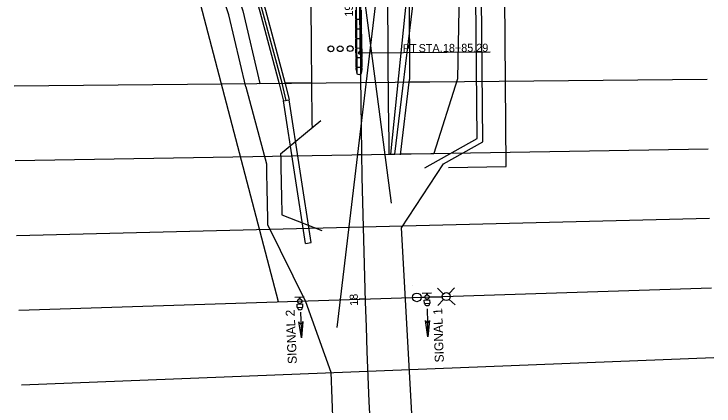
# Model space of a CAD drawing. Extents: x 2283072 to 2287933, y 586198 to 587702.
# Drawn here: x 2284314.5 to 2284556.9, y 586950.6 to 587086.3 of the extents above; entities that cross this region are included whole.
import ezdxf

# ---------------------------------------------------------------- set-up
doc = ezdxf.new("R2010")
doc.units = 0
for name, color, linetype in [('_CIVIL_CONSTRUCTION', 7, 'Continuous'), ('DR_X_Ditch', 7, 'Continuous'), ('DR_X_Headwall', 7, 'Continuous'), ('DT_X_Contour_Major', 7, 'Continuous'), ('DT_X_Terrain_Boundary', 7, 'Continuous'), ('DT_X_Void', 7, 'Continuous'), ('PF_X_Ground_Line', 7, 'Continuous'), ('PV_X_EOP', 7, 'Continuous'), ('RD_P_Fence', 7, 'Continuous'), ('RD_X_Gate', 7, 'Continuous'), ('RS_Raster1', 7, 'Continuous'), ('RW_P_Esmt_SH', 7, 'Continuous'), ('RW_P_Esmt_TMP', 7, 'Continuous'), ('SV_X_Break_Lines', 7, 'Continuous'), ('SV_X_Random_Point', 7, 'Continuous'), ('SV_X_Toe_of_Slope', 7, 'Continuous'), ('UT_X_Overhead_Telecom', 7, 'Continuous')]:
    doc.layers.add(name, color=color, linetype=linetype)

msp = doc.modelspace()

# ---------------------------------------------------------------- linework, layer by layer
at = {"layer": '_CIVIL_CONSTRUCTION'}
for p, q in [((2284442.67, 587114.69), (2284426.32, 586977.76)), ((2284452.67, 587114.75), (2284444.91, 587037.77)), ((2284433.32, 587065.57), (2284433.15, 587091.06)), ((2284434.49, 587091.07), (2284434.65, 587065.58)), ((2284432.86, 587084.56), (2284432.84, 587087.56)), ((2284434.86, 587084.57), (2284434.84, 587087.57)), ((2284432.86, 587084.56), (2284433.03, 587084.39)), ((2284433.03, 587084.39), (2284432.87, 587084.23)), ((2284432.89, 587081.23), (2284432.87, 587084.23)), ((2284434.7, 587084.41), (2284433.03, 587084.39)), ((2284434.86, 587084.57), (2284434.7, 587084.41)), ((2284434.7, 587084.41), (2284434.87, 587084.24)), ((2284434.89, 587081.24), (2284434.87, 587084.24)), ((2284432.89, 587081.23), (2284433.05, 587081.06)), ((2284433.05, 587081.06), (2284432.89, 587080.89)), ((2284432.91, 587077.89), (2284432.89, 587080.89)), ((2284434.72, 587081.07), (2284433.05, 587081.06)), ((2284434.89, 587081.24), (2284434.72, 587081.07)), ((2284434.72, 587081.07), (2284434.89, 587080.91)), ((2284434.91, 587077.91), (2284434.89, 587080.91)), ((2284432.91, 587077.89), (2284433.08, 587077.73)), ((2284433.08, 587077.73), (2284432.91, 587077.56)), ((2284434.74, 587077.74), (2284433.08, 587077.73)), ((2284434.91, 587077.91), (2284434.74, 587077.74)), ((2284434.74, 587077.74), (2284434.91, 587077.57)), ((2284432.93, 587074.56), (2284432.91, 587077.56)), ((2284434.93, 587074.57), (2284434.91, 587077.57)), ((2284432.93, 587074.56), (2284433.1, 587074.39)), ((2284433.1, 587074.39), (2284432.93, 587074.23)), ((2284432.95, 587071.23), (2284432.93, 587074.23)), ((2284434.76, 587074.41), (2284433.1, 587074.39)), ((2284434.93, 587074.57), (2284434.76, 587074.41)), ((2284434.76, 587074.41), (2284434.93, 587074.24)), ((2284434.93, 587074.24), (2284434.95, 587071.24)), ((2284432.95, 587071.23), (2284433.12, 587071.06)), ((2284433.12, 587071.06), (2284432.95, 587070.89)), ((2284432.97, 587067.89), (2284432.95, 587070.89)), ((2284434.79, 587071.07), (2284433.12, 587071.06)), ((2284434.95, 587071.24), (2284434.79, 587071.07)), ((2284434.79, 587071.07), (2284434.95, 587070.91)), ((2284434.95, 587070.91), (2284434.97, 587067.91)), ((2284432.97, 587067.89), (2284433.14, 587067.73)), ((2284433.14, 587067.73), (2284432.98, 587067.56)), ((2284432.98, 587067.12), (2284432.98, 587067.56)), ((2284432.98, 587067.12), (2284433.24, 587065.63)), ((2284434.81, 587067.74), (2284433.14, 587067.73)), ((2284434.98, 587067.14), (2284434.74, 587065.64)), ((2284434.97, 587067.91), (2284434.81, 587067.74)), ((2284434.81, 587067.74), (2284434.98, 587067.57)), ((2284434.98, 587067.57), (2284434.98, 587067.14))]:
    msp.add_line(p, q, dxfattribs=at)
for centre in [(2284424.28, 587074.23), (2284427.46, 587074.26), (2284430.92, 587074.29)]:
    msp.add_circle(centre, 1, dxfattribs=at)
msp.add_arc((2284433.98, 587066.74), 1.34, 236.1994, 304.5508, dxfattribs=at)
at = {"layer": 'DR_X_Ditch'}
msp.add_line((2284432.66, 587115.11), (2284445.17, 587020.81), dxfattribs=at)
at = {"layer": 'DR_X_Headwall'}
for p, q in [((2284476.87, 587042.07), (2284476.02, 587141.37)), ((2284394.76, 587061.12), (2284401.91, 587034.46)), ((2284463.26, 587034.38), (2284476.87, 587042.07))]:
    msp.add_line(p, q, dxfattribs=at)
for points in [[(2284394.76, 587061.12), (2284388.9, 587085.98), (2284380.59, 587111.27), (2284378.4, 587136.85), (2284376.37, 587161.77), (2284375.84, 587166.37), (2284371.09, 587185.68)], [(2284454.41, 586908.51), (2284448.73, 587012.28), (2284463.26, 587034.38)], [(2284402.35, 587013.4), (2284402.35, 587013.4), (2284415.5, 586986.74), (2284424.27, 586962.29), (2284426.3, 586906.97)]]:
    msp.add_lwpolyline(points, dxfattribs=at)
msp.add_arc((2287766.93, 587094.71), 3365.56, 181.02584, 181.38434, dxfattribs=at)
at = {"layer": 'DT_X_Contour_Major'}
for p, q in [((2284407.8, 587056.25), (2284409.78, 587056.56)), ((2284415.49, 587006.84), (2284407.8, 587056.25)), ((2284417.47, 587007.15), (2284409.78, 587056.56)), ((2284415.49, 587006.84), (2284417.47, 587007.15))]:
    msp.add_line(p, q, dxfattribs=at)
at = {"layer": 'DT_X_Terrain_Boundary'}
for p, q in [((2284442.59, 587278.55), (2284443.94, 587072.96)), ((2284446.36, 587037.79), (2284455.67, 587114.77)), ((2284444.36, 587037.77), (2284446.36, 587037.79))]:
    msp.add_line(p, q, dxfattribs=at)
msp.add_arc((2287766.93, 587094.71), 3323.06, 180.37508, 180.9819, dxfattribs=at)
at = {"layer": 'DT_X_Void'}
for p, q in [((2284314.53, 587061.44), (2284554.52, 587063.76)), ((2284314.88, 587035.55), (2284554.84, 587039.66)), ((2284315.42, 587009.65), (2284555.34, 587015.56)), ((2284316.15, 586983.76), (2284556.03, 586991.47)), ((2284317.08, 586957.88), (2284556.89, 586967.39))]:
    msp.add_line(p, q, dxfattribs=at)
at = {"layer": 'PF_X_Ground_Line'}
for p, q in [((2284463.17, 586989.44), (2284461.14, 586991.37)), ((2284465.15, 586989.49), (2284467.08, 586991.52)), ((2284411.79, 586988.23), (2284415.02, 586988.37)), ((2284411.79, 586988.23), (2284415.02, 586988.37)), ((2284413.28, 586988.29), (2284413.31, 586987.63)), ((2284413.28, 586988.29), (2284413.31, 586987.63)), ((2284413.52, 586988.3), (2284413.55, 586987.64)), ((2284413.52, 586988.3), (2284413.55, 586987.64)), ((2284455.52, 586988.25), (2284456.78, 586988.28)), ((2284455.87, 586989.66), (2284459.11, 586989.77)), ((2284457.37, 586989.71), (2284457.39, 586989.05)), ((2284457.37, 586989.71), (2284457.39, 586989.05)), ((2284457.61, 586989.72), (2284457.63, 586989.06)), ((2284457.61, 586989.72), (2284457.63, 586989.06)), ((2284458.3, 586988.33), (2284462.79, 586988.44)), ((2284412.54, 586985.84), (2284414.48, 586985.92)), ((2284412.54, 586985.84), (2284414.48, 586985.92)), ((2284412.59, 586984.69), (2284412.54, 586985.84)), ((2284412.59, 586984.69), (2284412.54, 586985.84)), ((2284413.38, 586986.14), (2284413.39, 586985.87)), ((2284413.38, 586986.14), (2284413.39, 586985.87)), ((2284413.62, 586986.15), (2284413.63, 586985.88)), ((2284413.62, 586986.15), (2284413.63, 586985.88)), ((2284414.53, 586984.78), (2284414.48, 586985.92)), ((2284414.53, 586984.78), (2284414.48, 586985.92)), ((2284456.6, 586987.26), (2284458.54, 586987.33)), ((2284456.64, 586986.12), (2284456.6, 586987.26)), ((2284456.64, 586986.12), (2284458.58, 586986.18)), ((2284456.91, 586985.64), (2284456.89, 586986.12)), ((2284456.91, 586985.64), (2284456.89, 586986.12)), ((2284457.44, 586987.56), (2284457.45, 586987.29)), ((2284457.44, 586987.56), (2284457.45, 586987.29)), ((2284457.68, 586987.56), (2284457.69, 586987.3)), ((2284457.68, 586987.56), (2284457.69, 586987.3)), ((2284458.35, 586985.68), (2284458.33, 586986.17)), ((2284458.35, 586985.68), (2284458.33, 586986.17)), ((2284458.58, 586986.18), (2284458.54, 586987.33)), ((2284463.22, 586987.46), (2284461.29, 586985.43)), ((2284465.2, 586987.51), (2284467.23, 586985.58)), ((2284412.59, 586984.69), (2284414.53, 586984.78)), ((2284412.59, 586984.69), (2284414.53, 586984.78)), ((2284412.86, 586984.21), (2284412.84, 586984.7)), ((2284412.86, 586984.21), (2284412.84, 586984.7)), ((2284413.7, 586983.13), (2284414.07, 586974.19)), ((2284414.3, 586984.28), (2284414.28, 586984.76)), ((2284414.3, 586984.28), (2284414.28, 586984.76)), ((2284457.53, 586984.2), (2284457.84, 586974.55)), ((2284414.07, 586974.19), (2284413.13, 586979.78)), ((2284414.54, 586979.84), (2284414.07, 586974.19)), ((2284457.84, 586974.55), (2284456.96, 586980.15)), ((2284458.36, 586980.19), (2284457.84, 586974.55))]:
    msp.add_line(p, q, dxfattribs=at)
for centre, radius in [((2284454.02, 586988.21), 1.5), ((2284457.54, 586988.31), 0.757), ((2284464.19, 586988.48), 1.4), ((2284413.47, 586986.89), 0.757), ((2284413.47, 586986.89), 0.757), ((2284413.47, 586986.89), 0.757), ((2284413.47, 586986.89), 0.757), ((2284413.47, 586986.89), 0.757), ((2284413.47, 586986.89), 0.757), ((2284413.47, 586986.89), 0.757), ((2284413.47, 586986.89), 0.757), ((2284413.47, 586986.89), 0.757), ((2284413.47, 586986.89), 0.757), ((2284413.47, 586986.89), 0.757), ((2284413.47, 586986.89), 0.757)]:
    msp.add_circle(centre, radius, dxfattribs=at)
for centre, radius, start, end in [((2284413.84, 586979.81), 0.702, 182.4261, 2.4261), ((2284457.66, 586980.17), 0.703, 181.8354, 1.8354)]:
    msp.add_arc(centre, radius, start, end, dxfattribs=at)
for centre, major_axis in [((2284457.63, 586985.66), (-0.72, -0.024)), ((2284457.63, 586985.66), (-0.72, -0.024)), ((2284413.58, 586984.24), (-0.72, -0.032)), ((2284413.58, 586984.24), (-0.72, -0.032))]:
    msp.add_ellipse(centre, major_axis=major_axis, ratio=0.45371, start_param=0, end_param=3.141593, dxfattribs=at)
at = {"layer": 'PV_X_EOP'}
msp.add_line((2284434.44, 587072.89), (2284479.44, 587073.19), dxfattribs=at)
msp.add_circle((2284434.44, 587072.89), 0.6, dxfattribs=at)
at = {"layer": 'RD_P_Fence'}
for p, q in [((2284474.86, 587043.23), (2284473.91, 587153.7)), ((2284456.77, 587033.01), (2284474.86, 587043.23))]:
    msp.add_line(p, q, dxfattribs=at)
at = {"layer": 'RD_X_Gate'}
msp.add_lwpolyline([(2284408.79, 587056.4), (2284407.32, 587062.34), (2284400.58, 587087.38), (2284393.52, 587112.33), (2284391.68, 587137.32), (2284389.59, 587162.31), (2284388.98, 587167.3), (2284389.06, 587187.31)], dxfattribs=at)
at = {"layer": 'RS_Raster1'}
for p, q in [((2284434.86, 587037.6), (2284433.66, 587037.58)), ((2284436.09, 586987.62), (2284434.09, 586987.55))]:
    msp.add_line(p, q, dxfattribs=at)
at = {"layer": 'RW_P_Esmt_SH'}
msp.add_line((2284406.11, 586986.65), (2284353.69, 587187.07), dxfattribs=at)
at = {"layer": 'RW_P_Esmt_TMP'}
for p, q in [((2284484.94, 587033.53), (2284483.91, 587153.38)), ((2284464.94, 587033.16), (2284484.94, 587033.53))]:
    msp.add_line(p, q, dxfattribs=at)
at = {"layer": 'SV_X_Break_Lines'}
msp.add_lwpolyline([(2284452.43, 586992.17), (2284452.43, 586992.17), (2284452.43, 586992.17)], close=True, dxfattribs=at)
at = {"layer": 'SV_X_Random_Point'}
msp.add_line((2284434.44, 587072.89), (2284433.09, 587278.49), dxfattribs=at)
msp.add_line((2284434.44, 587072.89), (2284433.09, 587278.49), dxfattribs=at)
msp.add_arc((2287766.93, 587094.71), 3332.56, 180.37508, 185.11985, dxfattribs=at)
msp.add_arc((2287766.93, 587094.71), 3332.56, 180.37508, 185.11985, dxfattribs=at)
at = {"layer": 'SV_X_Toe_of_Slope'}
for p, q in [((2284450.09, 587278.6), (2284451.5, 587063.67)), ((2284416.69, 587187.49), (2284417.44, 587072.78)), ((2284448.34, 587037.55), (2284451.5, 587063.67)), ((2284399.63, 587062.26), (2284406.29, 587062.33)), ((2284417.52, 587062.44), (2284408.35, 587062.35)), ((2284451.39, 587062.76), (2284467.8, 587062.92)), ((2284448.38, 587037.83), (2284459.9, 587038.03))]:
    msp.add_line(p, q, dxfattribs=at)
for points in [[(2284375.86, 587187.22), (2284380.77, 587167.25), (2284381.34, 587162.25), (2284383.38, 587137.27), (2284385.52, 587112.28), (2284393.71, 587087.33), (2284399.63, 587062.26)], [(2284388.06, 587187.3), (2284387.98, 587167.24), (2284388.6, 587162.21), (2284390.68, 587137.24), (2284392.53, 587112.16), (2284399.62, 587087.11), (2284406.36, 587062.09), (2284407.82, 587056.16)], [(2284390.06, 587187.31), (2284389.98, 587167.36), (2284390.59, 587162.41), (2284392.67, 587137.4), (2284394.51, 587112.51), (2284401.55, 587087.64), (2284408.29, 587062.59), (2284409.76, 587056.64)], [(2284469.36, 587137.83), (2284468.69, 587112.94), (2284468.5, 587087.92), (2284468.08, 587063.79), (2284459.9, 587038.03)]]:
    msp.add_lwpolyline(points, dxfattribs=at)
for centre, radius, start, end in [((2284434.44, 587072.89), 17, 180.37507254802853, 180.3750766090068), ((2287766.93, 587094.71), 3349.56, 180.37508, 180.81717)]:
    msp.add_arc(centre, radius, start, end, dxfattribs=at)
at = {"layer": 'UT_X_Overhead_Telecom'}
for p, q in [((2284406.85, 587037.88), (2284420.82, 587049.46)), ((2284407.27, 587016.82), (2284421.15, 587011.29))]:
    msp.add_line(p, q, dxfattribs=at)
msp.add_arc((2287766.93, 587094.71), 3360.56, 180.96902, 181.32807, dxfattribs=at)

# ---------------------------------------------------------------- texts
at = {"layer": 'PF_X_Ground_Line'}
for s, rotation, p in [('SIGNAL 2', 92.4261, (2284412.48, 586965.21)), ('SIGNAL 1', 91.8354, (2284463.36, 586965.71))]:
    msp.add_text(s, height=3.125, rotation=rotation, dxfattribs=at).set_placement(p)
at = {"layer": 'PV_X_EOP'}
for s, p in [('PT', (2284449.18, 587073.03)), (' STA. ', (2284453.59, 587073.06)), ('18+85.29', (2284463.04, 587073.12))]:
    msp.add_text(s, height=2.8, rotation=0.3751, dxfattribs=at).set_placement(p)
at = {"layer": 'RS_Raster1'}
for s, rotation, p in [('19', 90.3751, (2284431.86, 587085.38)), ('18', 91.8415, (2284433.66, 586985.32))]:
    msp.add_text(s, height=2.8, rotation=rotation, dxfattribs=at).set_placement(p)

doc.saveas('drawing.dxf')
